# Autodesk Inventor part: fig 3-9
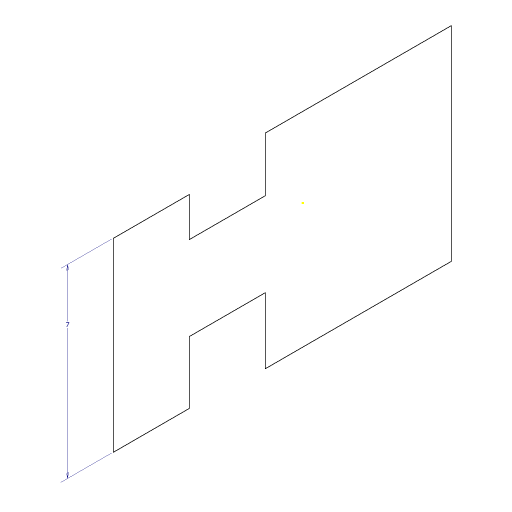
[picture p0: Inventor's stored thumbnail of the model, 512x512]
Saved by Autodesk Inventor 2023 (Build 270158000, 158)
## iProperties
Created: 2018-03
Part Number: fig 3-9
Material: Generic
Document SubType Name: Modeling
Designer: CADCIM 00
Density: 1 g/cm^3
Appearance: Default
Author: CADCIM 00
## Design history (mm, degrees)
sketch "Sketch1"
  geometry: L1 (-4.566, 7.164)-(2.434, 7.164); L2 (2.434, 7.164)-(2.434, 4.293); L3 (2.434, 4.293)-(0.957, 4.293); L4 (0.957, 4.293)-(0.957, 1.422); L5 (0.957, 1.422)-(3.008, 1.422); L6 (3.008, 1.422)-(3.008, -5.605); L7 (3.008, -5.605)-(-4.703, -5.605); L8 (-4.703, -5.605)-(-4.703, 1.422); L9 (-4.703, 1.422)-(-2.215, 1.422); L10 (-2.215, 1.422)-(-2.215, 4.293); L11 (-2.215, 4.293)-(-4.566, 4.293); L12 (-4.566, 4.293)-(-4.566, 7.164); 1 further point
  constraints: 24 end point, 9 perpendicular, 4 point on line, 1 horizontal
  dimensions: "d0" = 7 distance of L1.start L1.end
